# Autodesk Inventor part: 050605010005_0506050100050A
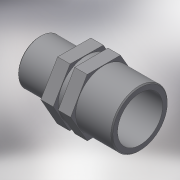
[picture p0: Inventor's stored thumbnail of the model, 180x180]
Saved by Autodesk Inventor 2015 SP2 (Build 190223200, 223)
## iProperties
Created: 2017-05
Part Number: 050605010005_0506050100050A
Material: Generic
Description: PLASSON REDUCING NIPPLE 1"-1/2"
Document SubType Name: Modeling
Designer: KIM
Density: 1 g/cm^3
Appearance: Default
Author: KIM
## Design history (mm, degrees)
derived "050605.ipt"
feature "Solid1::050605.ipt"
tag "TaggingFeature1"
body "Solid1"
other parameters: "d0" = 49, "d1" = 33.249, "d5" = 19, "d6" = 4.9, "d8" = 0.49, "d12" = 0, "d14" = 20.955, "d15" = 16.764, "d16" = 26.5992, "d17" = 16, "d18" = 2.45, "d19" = 36, "d21" = 0, "H_" = 49, "R_" = 33.249, "E_" = 36, "l_" = 19, "R_1" = 20.955, "l_1" = 16
